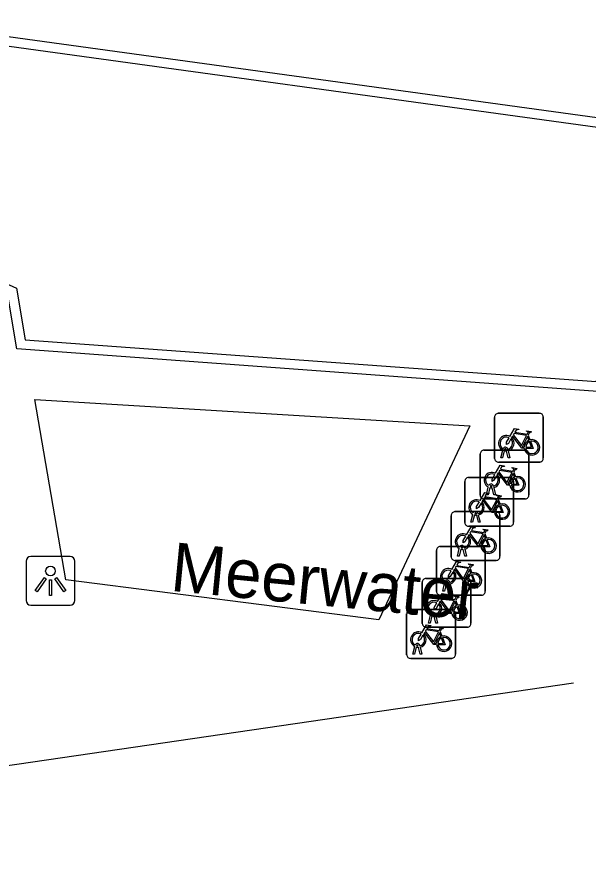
# Model space of a CAD drawing. Extents: x 155640 to 156810, y 382822 to 384046.
# Drawn here: x 156437.85 to 156449.58, y 383664.76 to 383681.91 of the extents above; entities that cross this region are included whole.
import ezdxf

# ---------------------------------------------------------------- set-up
doc = ezdxf.new("R2010")
doc.units = 0
for name, color, linetype in [('IMGEO_Fietsenrek', 7, 'Continuous'), ('IMGEO_Lichtpunt', 7, 'Continuous'), ('IMGEO_Lijnafwatering', 7, 'Continuous'), ('IMGEO_Muur', 7, 'Continuous'), ('IMGEO_Openbare_ruimte_label', 7, 'Continuous'), ('IMGEO_Voetgangersgebied_open', 7, 'Continuous')]:
    doc.layers.add(name, color=color, linetype=linetype)

msp = doc.modelspace()

# ---------------------------------------------------------------- linework, layer by layer
at = {"layer": 'IMGEO_Fietsenrek'}
for p, q in [((156447.729, 383673.77), (156448.57, 383673.77)), ((156448.57, 383673.77), (156447.729, 383673.77)), ((156447.654, 383672.845), (156447.654, 383673.686)), ((156447.654, 383673.686), (156447.654, 383672.845)), ((156448.654, 383673.695), (156448.654, 383672.854)), ((156448.654, 383672.854), (156448.654, 383673.695)), ((156448.341, 383673.319), (156448.377, 383673.224)), ((156447.923, 383673.037), (156447.924, 383673.03)), ((156447.359, 383672.089), (156447.359, 383672.93)), ((156447.359, 383672.93), (156447.359, 383672.089)), ((156447.434, 383673.014), (156448.275, 383673.014)), ((156448.275, 383673.014), (156447.434, 383673.014)), ((156447.781, 383672.854), (156447.82, 383673.014)), ((156447.85, 383673.002), (156447.815, 383672.854)), ((156447.892, 383673.026), (156447.891, 383673.03)), ((156447.933, 383672.854), (156447.899, 383672.996)), ((156447.931, 383673), (156447.966, 383672.854)), ((156448.359, 383672.939), (156448.359, 383672.098)), ((156448.359, 383672.098), (156448.359, 383672.939)), ((156448.579, 383672.77), (156447.738, 383672.77)), ((156447.738, 383672.77), (156448.579, 383672.77)), ((156447.815, 383672.854), (156447.781, 383672.854)), ((156447.966, 383672.854), (156447.933, 383672.854)), ((156448.046, 383672.563), (156448.082, 383672.468)), ((156447.043, 383671.527), (156447.043, 383672.368)), ((156447.043, 383672.368), (156447.043, 383671.527)), ((156447.118, 383672.452), (156447.959, 383672.452)), ((156447.959, 383672.452), (156447.118, 383672.452)), ((156448.043, 383672.377), (156448.043, 383671.536)), ((156448.043, 383671.536), (156448.043, 383672.377)), ((156447.486, 383672.098), (156447.525, 383672.258)), ((156447.555, 383672.246), (156447.52, 383672.098)), ((156447.597, 383672.27), (156447.596, 383672.274)), ((156447.638, 383672.098), (156447.604, 383672.24)), ((156447.628, 383672.281), (156447.629, 383672.274)), ((156447.636, 383672.244), (156447.671, 383672.098)), ((156448.284, 383672.014), (156447.443, 383672.014)), ((156447.443, 383672.014), (156448.284, 383672.014)), ((156447.52, 383672.098), (156447.486, 383672.098)), ((156447.671, 383672.098), (156447.638, 383672.098)), ((156447.73, 383672.001), (156447.766, 383671.906)), ((156446.764, 383670.827), (156446.764, 383671.668)), ((156446.764, 383671.668), (156446.764, 383670.827)), ((156446.839, 383671.752), (156447.68, 383671.752)), ((156447.68, 383671.752), (156446.839, 383671.752)), ((156447.17, 383671.536), (156447.209, 383671.696)), ((156447.239, 383671.684), (156447.204, 383671.536)), ((156447.281, 383671.708), (156447.28, 383671.712)), ((156447.322, 383671.536), (156447.288, 383671.678)), ((156447.312, 383671.719), (156447.313, 383671.712)), ((156447.32, 383671.682), (156447.355, 383671.536)), ((156447.764, 383671.677), (156447.764, 383670.836)), ((156447.764, 383670.836), (156447.764, 383671.677)), ((156447.204, 383671.536), (156447.17, 383671.536)), ((156447.355, 383671.536), (156447.322, 383671.536)), ((156447.968, 383671.452), (156447.127, 383671.452)), ((156447.127, 383671.452), (156447.968, 383671.452)), ((156447.451, 383671.301), (156447.487, 383671.206)), ((156446.538, 383671.039), (156447.379, 383671.039)), ((156447.379, 383671.039), (156446.538, 383671.039)), ((156446.891, 383670.836), (156446.93, 383670.996)), ((156446.96, 383670.984), (156446.925, 383670.836)), ((156447.002, 383671.008), (156447.001, 383671.012)), ((156447.043, 383670.836), (156447.009, 383670.978)), ((156447.033, 383671.019), (156447.034, 383671.012)), ((156447.041, 383670.982), (156447.076, 383670.836)), ((156446.463, 383670.114), (156446.463, 383670.955)), ((156446.463, 383670.955), (156446.463, 383670.114)), ((156446.925, 383670.836), (156446.891, 383670.836)), ((156447.076, 383670.836), (156447.043, 383670.836)), ((156447.463, 383670.964), (156447.463, 383670.123)), ((156447.463, 383670.123), (156447.463, 383670.964)), ((156447.689, 383670.752), (156446.848, 383670.752)), ((156446.848, 383670.752), (156447.689, 383670.752)), ((156447.15, 383670.588), (156447.186, 383670.493)), ((156446.17, 383669.457), (156446.17, 383670.298)), ((156446.17, 383670.298), (156446.17, 383669.457)), ((156446.245, 383670.382), (156447.086, 383670.382)), ((156447.086, 383670.382), (156446.245, 383670.382)), ((156446.701, 383670.295), (156446.7, 383670.299)), ((156446.732, 383670.306), (156446.733, 383670.299)), ((156447.17, 383670.307), (156447.17, 383669.466)), ((156447.17, 383669.466), (156447.17, 383670.307)), ((156446.59, 383670.123), (156446.629, 383670.283)), ((156446.624, 383670.123), (156446.59, 383670.123)), ((156446.659, 383670.271), (156446.624, 383670.123)), ((156446.742, 383670.123), (156446.708, 383670.265)), ((156446.74, 383670.269), (156446.775, 383670.123)), ((156446.775, 383670.123), (156446.742, 383670.123)), ((156447.388, 383670.039), (156446.547, 383670.039)), ((156446.547, 383670.039), (156447.388, 383670.039)), ((156446.857, 383669.931), (156446.893, 383669.836)), ((156445.85, 383668.816), (156445.85, 383669.657)), ((156445.85, 383669.657), (156445.85, 383668.816)), ((156445.925, 383669.741), (156446.766, 383669.741)), ((156446.766, 383669.741), (156445.925, 383669.741)), ((156446.297, 383669.466), (156446.336, 383669.626)), ((156446.366, 383669.614), (156446.331, 383669.466)), ((156446.408, 383669.638), (156446.407, 383669.642)), ((156446.449, 383669.466), (156446.415, 383669.608)), ((156446.439, 383669.649), (156446.44, 383669.642)), ((156446.447, 383669.612), (156446.482, 383669.466)), ((156446.85, 383669.666), (156446.85, 383668.825)), ((156446.85, 383668.825), (156446.85, 383669.666)), ((156446.331, 383669.466), (156446.297, 383669.466)), ((156446.482, 383669.466), (156446.449, 383669.466)), ((156447.095, 383669.382), (156446.254, 383669.382)), ((156446.254, 383669.382), (156447.095, 383669.382)), ((156446.537, 383669.29), (156446.573, 383669.195)), ((156445.977, 383668.825), (156446.016, 383668.985)), ((156446.046, 383668.973), (156446.011, 383668.825)), ((156446.088, 383668.997), (156446.087, 383669.001)), ((156446.129, 383668.825), (156446.095, 383668.967)), ((156446.119, 383669.008), (156446.12, 383669.001)), ((156446.127, 383668.971), (156446.162, 383668.825)), ((156446.011, 383668.825), (156445.977, 383668.825)), ((156446.162, 383668.825), (156446.129, 383668.825)), ((156446.775, 383668.741), (156445.934, 383668.741)), ((156445.934, 383668.741), (156446.775, 383668.741))]:
    msp.add_line(p, q, dxfattribs=at)
for points in [[(156447.967, 383673.296), (156448.062, 383673.46), (156448.148, 383673.446), (156448.15, 383673.437), (156448.094, 383673.426), (156448.067, 383673.381), (156448.323, 383673.34)], [(156448.323, 383673.34), (156448.348, 383673.389), (156448.342, 383673.393), (156448.319, 383673.397), (156448.307, 383673.404), (156448.306, 383673.407), (156448.308, 383673.412), (156448.403, 383673.397), (156448.405, 383673.387), (156448.395, 383673.374), (156448.383, 383673.368), (156448.369, 383673.374), (156448.341, 383673.319)], [(156447.988, 383673.244), (156447.936, 383673.154), (156447.896, 383673.129), (156447.897, 383673.176), (156447.952, 383673.27)], [(156448.263, 383673.052), (156448.213, 383673.052), (156448.022, 383673.303), (156448.003, 383673.271)], [(156448.31, 383673.315), (156448.053, 383673.356), (156448.036, 383673.327), (156448.203, 383673.107), (156448.31, 383673.315)], [(156448.358, 383673.217), (156448.328, 383673.294), (156448.219, 383673.076), (156448.262, 383673.076)], [(156448.292, 383673.076), (156448.412, 383673.075), (156448.368, 383673.189)], [(156448.388, 383673.196), (156448.443, 383673.051), (156448.293, 383673.051)], [(156447.672, 383672.54), (156447.767, 383672.704), (156447.853, 383672.69), (156447.855, 383672.681), (156447.799, 383672.67), (156447.772, 383672.625), (156448.028, 383672.584)], [(156447.968, 383672.296), (156447.918, 383672.296), (156447.727, 383672.547), (156447.708, 383672.515)], [(156448.015, 383672.559), (156447.758, 383672.6), (156447.741, 383672.571), (156447.908, 383672.351), (156448.015, 383672.559)], [(156448.063, 383672.461), (156448.033, 383672.538), (156447.924, 383672.32), (156447.967, 383672.32)], [(156448.028, 383672.584), (156448.053, 383672.633), (156448.047, 383672.637), (156448.024, 383672.641), (156448.012, 383672.648), (156448.011, 383672.651), (156448.013, 383672.656), (156448.108, 383672.641), (156448.11, 383672.631), (156448.1, 383672.618), (156448.088, 383672.612), (156448.074, 383672.618), (156448.046, 383672.563)], [(156447.693, 383672.488), (156447.641, 383672.398), (156447.601, 383672.373), (156447.602, 383672.42), (156447.657, 383672.514)], [(156447.997, 383672.32), (156448.117, 383672.319), (156448.073, 383672.433)], [(156448.093, 383672.44), (156448.148, 383672.295), (156447.998, 383672.295)], [(156447.356, 383671.978), (156447.451, 383672.142), (156447.537, 383672.128), (156447.539, 383672.119), (156447.483, 383672.108), (156447.456, 383672.063), (156447.712, 383672.022)], [(156447.699, 383671.997), (156447.442, 383672.038), (156447.425, 383672.009), (156447.592, 383671.789), (156447.699, 383671.997)], [(156447.712, 383672.022), (156447.737, 383672.071), (156447.731, 383672.075), (156447.708, 383672.079), (156447.696, 383672.086), (156447.695, 383672.089), (156447.697, 383672.094), (156447.792, 383672.079), (156447.794, 383672.069), (156447.784, 383672.056), (156447.772, 383672.05), (156447.758, 383672.056), (156447.73, 383672.001)], [(156447.377, 383671.926), (156447.325, 383671.836), (156447.285, 383671.811), (156447.286, 383671.858), (156447.341, 383671.952)], [(156447.652, 383671.734), (156447.602, 383671.734), (156447.411, 383671.985), (156447.392, 383671.953)], [(156447.747, 383671.899), (156447.717, 383671.976), (156447.608, 383671.758), (156447.651, 383671.758)], [(156447.681, 383671.758), (156447.801, 383671.757), (156447.757, 383671.871)], [(156447.777, 383671.878), (156447.832, 383671.733), (156447.682, 383671.733)], [(156447.077, 383671.278), (156447.172, 383671.442), (156447.258, 383671.428), (156447.26, 383671.419), (156447.204, 383671.408), (156447.177, 383671.363), (156447.433, 383671.322)], [(156447.42, 383671.297), (156447.163, 383671.338), (156447.146, 383671.309), (156447.313, 383671.089), (156447.42, 383671.297)], [(156447.433, 383671.322), (156447.458, 383671.371), (156447.452, 383671.375), (156447.429, 383671.379), (156447.417, 383671.386), (156447.416, 383671.389), (156447.418, 383671.394), (156447.513, 383671.379), (156447.515, 383671.369), (156447.505, 383671.356), (156447.493, 383671.35), (156447.479, 383671.356), (156447.451, 383671.301)], [(156447.098, 383671.226), (156447.046, 383671.136), (156447.006, 383671.111), (156447.007, 383671.158), (156447.062, 383671.252)], [(156447.373, 383671.034), (156447.323, 383671.034), (156447.132, 383671.285), (156447.113, 383671.253)], [(156447.468, 383671.199), (156447.438, 383671.276), (156447.329, 383671.058), (156447.372, 383671.058)], [(156447.402, 383671.058), (156447.522, 383671.057), (156447.478, 383671.171)], [(156447.498, 383671.178), (156447.553, 383671.033), (156447.403, 383671.033)], [(156446.776, 383670.565), (156446.871, 383670.729), (156446.957, 383670.715), (156446.959, 383670.706), (156446.903, 383670.695), (156446.876, 383670.65), (156447.132, 383670.609)], [(156447.132, 383670.609), (156447.157, 383670.658), (156447.151, 383670.662), (156447.128, 383670.666), (156447.116, 383670.673), (156447.115, 383670.676), (156447.117, 383670.681), (156447.212, 383670.666), (156447.214, 383670.656), (156447.204, 383670.643), (156447.192, 383670.637), (156447.178, 383670.643), (156447.15, 383670.588)], [(156446.797, 383670.513), (156446.745, 383670.423), (156446.705, 383670.398), (156446.706, 383670.445), (156446.761, 383670.539)], [(156447.072, 383670.321), (156447.022, 383670.321), (156446.831, 383670.572), (156446.812, 383670.54)], [(156447.119, 383670.584), (156446.862, 383670.625), (156446.845, 383670.596), (156447.012, 383670.376), (156447.119, 383670.584)], [(156447.167, 383670.486), (156447.137, 383670.563), (156447.028, 383670.345), (156447.071, 383670.345)], [(156447.197, 383670.465), (156447.252, 383670.32), (156447.102, 383670.32)], [(156447.101, 383670.345), (156447.221, 383670.344), (156447.177, 383670.458)], [(156446.483, 383669.908), (156446.578, 383670.072), (156446.664, 383670.058), (156446.666, 383670.049), (156446.61, 383670.038), (156446.583, 383669.993), (156446.839, 383669.952)], [(156446.826, 383669.927), (156446.569, 383669.968), (156446.552, 383669.939), (156446.719, 383669.719), (156446.826, 383669.927)], [(156446.839, 383669.952), (156446.864, 383670.001), (156446.858, 383670.005), (156446.835, 383670.009), (156446.823, 383670.016), (156446.822, 383670.019), (156446.824, 383670.024), (156446.919, 383670.009), (156446.921, 383669.999), (156446.911, 383669.986), (156446.899, 383669.98), (156446.885, 383669.986), (156446.857, 383669.931)], [(156446.504, 383669.856), (156446.452, 383669.766), (156446.412, 383669.741), (156446.413, 383669.788), (156446.468, 383669.882)], [(156446.779, 383669.664), (156446.729, 383669.664), (156446.538, 383669.915), (156446.519, 383669.883)], [(156446.874, 383669.829), (156446.844, 383669.906), (156446.735, 383669.688), (156446.778, 383669.688)], [(156446.808, 383669.688), (156446.928, 383669.687), (156446.884, 383669.801)], [(156446.904, 383669.808), (156446.959, 383669.663), (156446.809, 383669.663)], [(156446.163, 383669.267), (156446.258, 383669.431), (156446.344, 383669.417), (156446.346, 383669.408), (156446.29, 383669.397), (156446.263, 383669.352), (156446.519, 383669.311)], [(156446.459, 383669.023), (156446.409, 383669.023), (156446.218, 383669.274), (156446.199, 383669.242)], [(156446.506, 383669.286), (156446.249, 383669.327), (156446.232, 383669.298), (156446.399, 383669.078), (156446.506, 383669.286)], [(156446.554, 383669.188), (156446.524, 383669.265), (156446.415, 383669.047), (156446.458, 383669.047)], [(156446.519, 383669.311), (156446.544, 383669.36), (156446.538, 383669.364), (156446.515, 383669.368), (156446.503, 383669.375), (156446.502, 383669.378), (156446.504, 383669.383), (156446.599, 383669.368), (156446.601, 383669.358), (156446.591, 383669.345), (156446.579, 383669.339), (156446.565, 383669.345), (156446.537, 383669.29)], [(156446.184, 383669.215), (156446.132, 383669.125), (156446.092, 383669.1), (156446.093, 383669.147), (156446.148, 383669.241)], [(156446.488, 383669.047), (156446.608, 383669.046), (156446.564, 383669.16)], [(156446.584, 383669.167), (156446.639, 383669.022), (156446.489, 383669.022)]]:
    msp.add_lwpolyline(points, dxfattribs=at)
for centre, radius, start, end in [((156447.732, 383673.692), 0.0779, 92.4484, 184.2845), ((156447.732, 383673.692), 0.0779, 92.4484, 184.2845), ((156448.576, 383673.692), 0.0779, 2.4484, 94.2845), ((156448.576, 383673.692), 0.0779, 2.4484, 94.2845), ((156447.894, 383673.155), 0.159, 62.6766, 242.1369), ((156447.894, 383673.155), 0.129, 63.3192, 238.903), ((156447.894, 383673.155), 0.129, 283.6043, 43.4302), ((156447.894, 383673.155), 0.159, 283.5766, 46.6042), ((156448.421, 383673.071), 0.159, 113.3408, 178.3217), ((156448.421, 383673.071), 0.159, 187.0065, 105.7708), ((156447.874, 383673.026), 0.0499, 12.8025, 158.6934), ((156447.874, 383673.026), 0.0174, 12.8025, 163.4502), ((156448.421, 383673.071), 0.129, 113.923, 177.9556), ((156448.421, 383673.071), 0.129, 188.6715, 104.5883), ((156447.437, 383672.936), 0.0779, 92.4484, 184.2845), ((156447.437, 383672.936), 0.0779, 92.4484, 184.2845), ((156447.894, 383673.155), 0.159, 253.9967, 271.7867), ((156447.894, 383673.155), 0.129, 253.415, 269.0204), ((156448.281, 383672.936), 0.0779, 2.4484, 94.2845), ((156448.281, 383672.936), 0.0779, 2.4484, 94.2845), ((156447.732, 383672.848), 0.0779, 182.4484, 274.2845), ((156447.732, 383672.848), 0.0779, 182.4484, 274.2845), ((156448.576, 383672.848), 0.0779, 272.4484, 4.2845), ((156448.576, 383672.848), 0.0779, 272.4484, 4.2845), ((156447.599, 383672.399), 0.159, 62.6766, 242.1369), ((156447.599, 383672.399), 0.129, 63.3192, 238.903), ((156447.121, 383672.374), 0.0779, 92.4484, 184.2845), ((156447.121, 383672.374), 0.0779, 92.4484, 184.2845), ((156447.599, 383672.399), 0.129, 283.6043, 43.4302), ((156447.599, 383672.399), 0.159, 283.5766, 46.6042), ((156447.965, 383672.374), 0.0779, 2.4484, 94.2845), ((156447.965, 383672.374), 0.0779, 2.4484, 94.2845), ((156448.126, 383672.315), 0.159, 113.3408, 178.3217), ((156448.126, 383672.315), 0.159, 187.0065, 105.7708), ((156448.126, 383672.315), 0.129, 113.923, 177.9556), ((156448.126, 383672.315), 0.129, 188.6715, 104.5883), ((156447.579, 383672.27), 0.0499, 12.8025, 158.6934), ((156447.599, 383672.399), 0.159, 253.9967, 271.7867), ((156447.579, 383672.27), 0.0174, 12.8025, 163.4502), ((156447.599, 383672.399), 0.129, 253.415, 269.0204), ((156447.437, 383672.092), 0.0779, 182.4484, 274.2845), ((156447.437, 383672.092), 0.0779, 182.4484, 274.2845), ((156448.281, 383672.092), 0.0779, 272.4484, 4.2845), ((156448.281, 383672.092), 0.0779, 272.4484, 4.2845), ((156447.283, 383671.837), 0.159, 62.6766, 242.1369), ((156447.283, 383671.837), 0.129, 63.3192, 238.903), ((156447.283, 383671.837), 0.129, 283.6043, 43.4302), ((156447.283, 383671.837), 0.159, 283.5766, 46.6042), ((156447.81, 383671.753), 0.159, 113.3408, 178.3217), ((156447.81, 383671.753), 0.159, 187.0065, 105.7708), ((156447.81, 383671.753), 0.129, 113.923, 177.9556), ((156447.81, 383671.753), 0.129, 188.6715, 104.5883), ((156446.842, 383671.674), 0.0779, 92.4484, 184.2845), ((156446.842, 383671.674), 0.0779, 92.4484, 184.2845), ((156447.263, 383671.708), 0.0499, 12.8025, 158.6934), ((156447.283, 383671.837), 0.159, 253.9967, 271.7867), ((156447.263, 383671.708), 0.0174, 12.8025, 163.4502), ((156447.283, 383671.837), 0.129, 253.415, 269.0204), ((156447.686, 383671.674), 0.0779, 2.4484, 94.2845), ((156447.686, 383671.674), 0.0779, 2.4484, 94.2845), ((156447.121, 383671.53), 0.0779, 182.4484, 274.2845), ((156447.121, 383671.53), 0.0779, 182.4484, 274.2845), ((156447.965, 383671.53), 0.0779, 272.4484, 4.2845), ((156447.965, 383671.53), 0.0779, 272.4484, 4.2845), ((156447.004, 383671.137), 0.159, 62.6766, 242.1369), ((156447.004, 383671.137), 0.129, 63.3192, 238.903), ((156447.004, 383671.137), 0.129, 283.6043, 43.4302), ((156447.004, 383671.137), 0.159, 283.5766, 46.6042), ((156447.531, 383671.053), 0.159, 113.3408, 178.3217), ((156447.531, 383671.053), 0.159, 187.0065, 105.7708), ((156447.531, 383671.053), 0.129, 113.923, 177.9556), ((156447.531, 383671.053), 0.129, 188.6715, 104.5883), ((156446.541, 383670.961), 0.0779, 92.4484, 184.2845), ((156446.541, 383670.961), 0.0779, 92.4484, 184.2845), ((156446.984, 383671.008), 0.0499, 12.8025, 158.6934), ((156447.004, 383671.137), 0.159, 253.9967, 271.7867), ((156446.984, 383671.008), 0.0174, 12.8025, 163.4502), ((156447.004, 383671.137), 0.129, 253.415, 269.0204), ((156447.385, 383670.961), 0.0779, 2.4484, 94.2845), ((156447.385, 383670.961), 0.0779, 2.4484, 94.2845), ((156446.842, 383670.83), 0.0779, 182.4484, 274.2845), ((156446.842, 383670.83), 0.0779, 182.4484, 274.2845), ((156447.686, 383670.83), 0.0779, 272.4484, 4.2845), ((156447.686, 383670.83), 0.0779, 272.4484, 4.2845), ((156446.703, 383670.424), 0.159, 62.6766, 242.1369), ((156446.703, 383670.424), 0.129, 63.3192, 238.903), ((156446.703, 383670.424), 0.129, 283.6043, 43.4302), ((156446.703, 383670.424), 0.159, 283.5766, 46.6042), ((156447.23, 383670.34), 0.159, 113.3408, 178.3217), ((156447.23, 383670.34), 0.159, 187.0065, 105.7708), ((156447.23, 383670.34), 0.129, 188.6715, 104.5883), ((156446.248, 383670.304), 0.0779, 92.4484, 184.2845), ((156446.248, 383670.304), 0.0779, 92.4484, 184.2845), ((156446.683, 383670.295), 0.0499, 12.8025, 158.6934), ((156446.683, 383670.295), 0.0174, 12.8025, 163.4502), ((156446.703, 383670.424), 0.129, 253.415, 269.0204), ((156447.092, 383670.304), 0.0779, 2.4484, 94.2845), ((156447.092, 383670.304), 0.0779, 2.4484, 94.2845), ((156447.23, 383670.34), 0.129, 113.923, 177.9556), ((156446.703, 383670.424), 0.159, 253.9967, 271.7867), ((156447.385, 383670.117), 0.0779, 272.4484, 4.2845), ((156447.385, 383670.117), 0.0779, 272.4484, 4.2845), ((156446.541, 383670.117), 0.0779, 182.4484, 274.2845), ((156446.541, 383670.117), 0.0779, 182.4484, 274.2845), ((156446.41, 383669.767), 0.159, 62.6766, 242.1369), ((156446.41, 383669.767), 0.129, 63.3192, 238.903), ((156446.41, 383669.767), 0.129, 283.6043, 43.4302), ((156446.41, 383669.767), 0.159, 283.5766, 46.6042), ((156446.937, 383669.683), 0.159, 113.3408, 178.3217), ((156446.937, 383669.683), 0.159, 187.0065, 105.7708), ((156446.937, 383669.683), 0.129, 113.923, 177.9556), ((156446.937, 383669.683), 0.129, 188.6715, 104.5883), ((156445.928, 383669.663), 0.0779, 92.4484, 184.2845), ((156445.928, 383669.663), 0.0779, 92.4484, 184.2845), ((156446.39, 383669.638), 0.0499, 12.8025, 158.6934), ((156446.41, 383669.767), 0.159, 253.9967, 271.7867), ((156446.39, 383669.638), 0.0174, 12.8025, 163.4502), ((156446.41, 383669.767), 0.129, 253.415, 269.0204), ((156446.772, 383669.663), 0.0779, 2.4484, 94.2845), ((156446.772, 383669.663), 0.0779, 2.4484, 94.2845), ((156446.248, 383669.46), 0.0779, 182.4484, 274.2845), ((156446.248, 383669.46), 0.0779, 182.4484, 274.2845), ((156447.092, 383669.46), 0.0779, 272.4484, 4.2845), ((156447.092, 383669.46), 0.0779, 272.4484, 4.2845), ((156446.09, 383669.126), 0.159, 62.6766, 242.1369), ((156446.09, 383669.126), 0.129, 63.3192, 238.903), ((156446.09, 383669.126), 0.129, 283.6043, 43.4302), ((156446.09, 383669.126), 0.159, 283.5766, 46.6042), ((156446.617, 383669.042), 0.159, 113.3408, 178.3217), ((156446.617, 383669.042), 0.159, 187.0065, 105.7708), ((156446.617, 383669.042), 0.129, 113.923, 177.9556), ((156446.617, 383669.042), 0.129, 188.6715, 104.5883), ((156446.07, 383668.997), 0.0499, 12.8025, 158.6934), ((156446.09, 383669.126), 0.159, 253.9967, 271.7867), ((156446.07, 383668.997), 0.0174, 12.8025, 163.4502), ((156446.09, 383669.126), 0.129, 253.415, 269.0204), ((156445.928, 383668.819), 0.0779, 182.4484, 274.2845), ((156445.928, 383668.819), 0.0779, 182.4484, 274.2845), ((156446.772, 383668.819), 0.0779, 272.4484, 4.2845), ((156446.772, 383668.819), 0.0779, 272.4484, 4.2845)]:
    msp.add_arc(centre, radius, start, end, dxfattribs=at)
at = {"layer": 'IMGEO_Lichtpunt'}
for p, q in [((156438.945, 383670.83), (156438.137, 383670.83)), ((156438.945, 383670.83), (156438.137, 383670.83)), ((156438.043, 383670.735), (156438.043, 383669.928)), ((156438.043, 383670.735), (156438.043, 383669.928)), ((156439.039, 383669.928), (156439.039, 383670.735)), ((156439.039, 383669.928), (156439.039, 383670.735)), ((156438.137, 383669.834), (156438.945, 383669.834)), ((156438.137, 383669.834), (156438.945, 383669.834))]:
    msp.add_line(p, q, dxfattribs=at)
for points in [[(156438.417, 383670.399), (156438.456, 383670.371), (156438.268, 383670.109), (156438.23, 383670.136), (156438.417, 383670.399)], [(156438.519, 383670.351), (156438.566, 383670.351), (156438.566, 383670.029), (156438.519, 383670.029), (156438.519, 383670.351)], [(156438.629, 383670.371), (156438.667, 383670.398), (156438.854, 383670.136), (156438.815, 383670.108), (156438.629, 383670.371)]]:
    msp.add_lwpolyline(points, dxfattribs=at)
msp.add_circle((156438.542, 383670.533), 0.0994, dxfattribs=at)
for centre, start, end in [((156438.137, 383670.735), 90, 180), ((156438.137, 383670.735), 90, 180), ((156438.945, 383670.735), 0, 90), ((156438.945, 383670.735), 0, 90), ((156438.137, 383669.928), 180, 270), ((156438.137, 383669.928), 180, 270), ((156438.945, 383669.928), 270, 0), ((156438.945, 383669.928), 270, 360)]:
    msp.add_arc(centre, 0.0946, start, end, dxfattribs=at)
at = {"layer": 'IMGEO_Lijnafwatering'}
msp.add_lwpolyline([(156449.271, 383668.233), (156425.533, 383664.761)], dxfattribs=at)
at = {"layer": 'IMGEO_Muur'}
for points in [[(156449.862, 383674.213), (156437.854, 383675.092), (156437.664, 383676.198), (156433.231, 383678.215), (156434.73, 383681.91), (156452.347, 383679.484), (156449.862, 383674.213)], [(156449.74, 383674.423), (156452.05, 383679.323), (156434.857, 383681.691), (156433.488, 383678.317), (156437.843, 383676.337), (156438.025, 383675.28), (156449.74, 383674.423)]]:
    msp.add_lwpolyline(points, dxfattribs=at)
at = {"layer": 'IMGEO_Voetgangersgebied_open'}
msp.add_lwpolyline([(156438.858, 383670.354), (156438.221, 383674.055), (156447.147, 383673.516), (156445.279, 383669.529), (156438.858, 383670.354)], dxfattribs=at)

# ---------------------------------------------------------------- texts
at = {"layer": 'IMGEO_Openbare_ruimte_label'}
msp.add_text('Meerwater', height=1, rotation=354.432, dxfattribs=at).set_placement((156440.982, 383670.129))

doc.saveas('drawing.dxf')
